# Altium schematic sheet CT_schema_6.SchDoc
size 299 x 185 mm
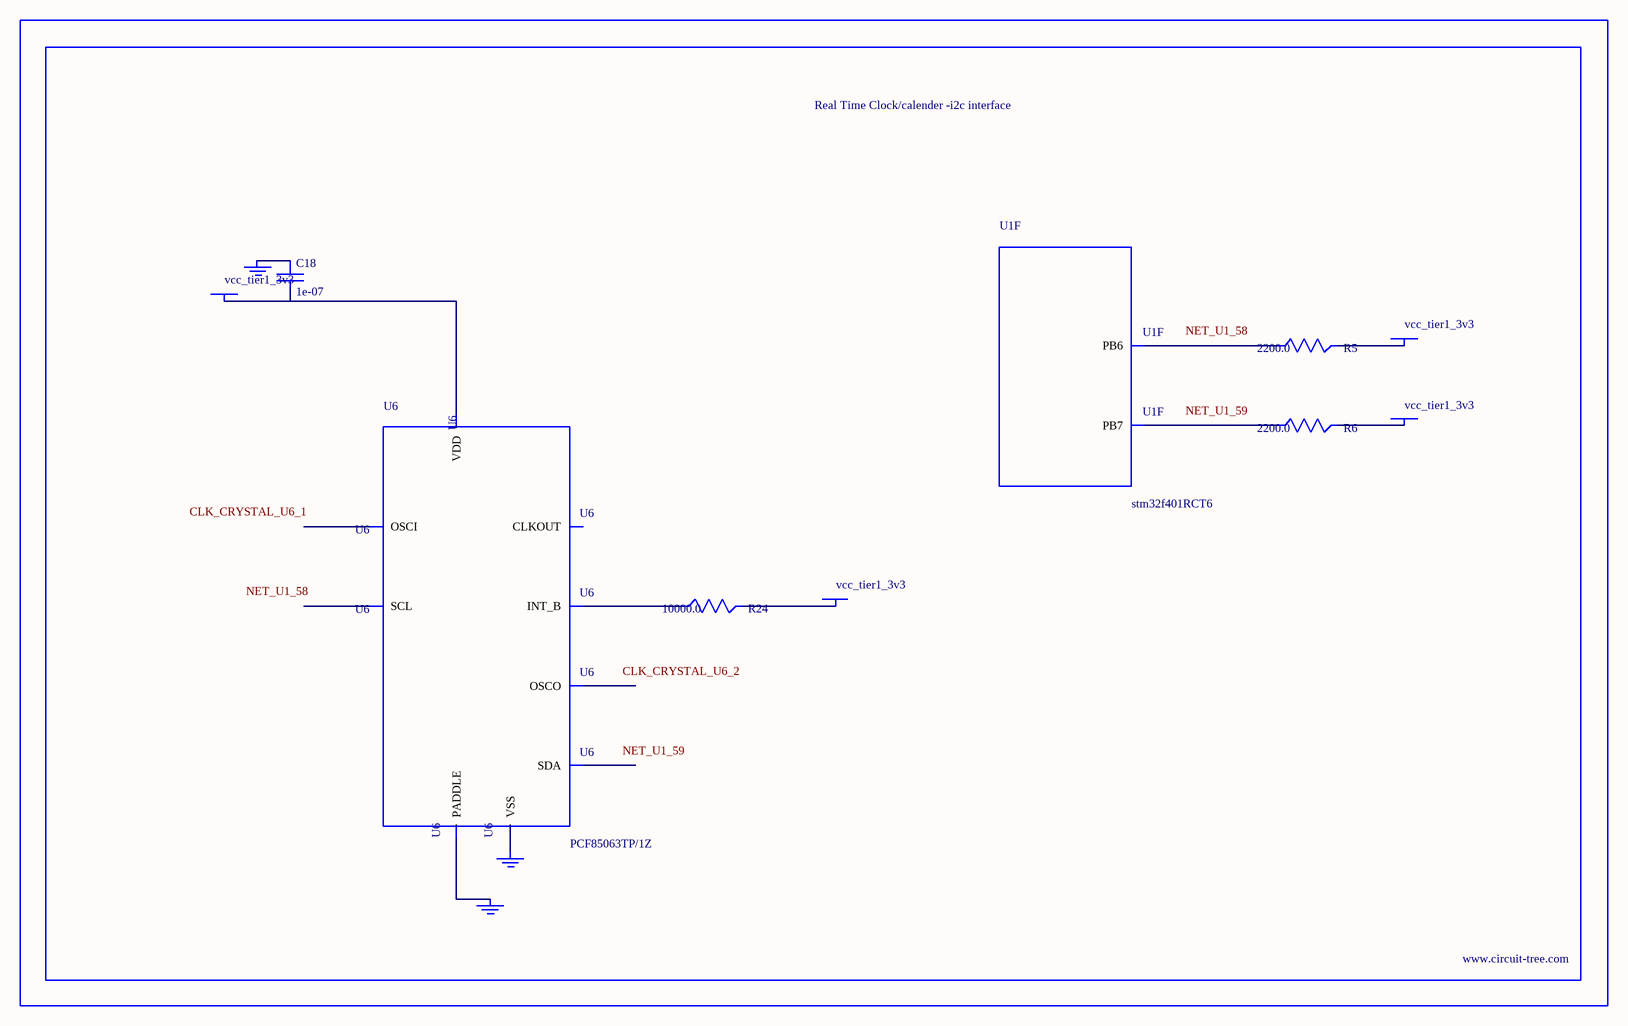
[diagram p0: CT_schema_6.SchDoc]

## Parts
BORDER5  (no value)
C18  1e-07  [C0402]
GND_INSTANCE_5_0  (no value)
GND_INSTANCE_5_1  (no value)
GND_INSTANCE_5_2  (no value)
POWER_INSTANCE_5_0  vcc_tier1_3v3
POWER_INSTANCE_5_1  vcc_tier1_3v3
POWER_INSTANCE_5_2  vcc_tier1_3v3
POWER_INSTANCE_5_3  vcc_tier1_3v3
R5  2200.0  [R0603]
R6  2200.0  [R0603]
R24  10000.0  [R0603]
U1  stm32f401RCT6  [LQFP64]  (part F of 9)
U6  PCF85063TP/1Z  [SON-8]

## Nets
NetC18_1: C18.1 GND_INSTANCE_5_0.0(GND)
NetC18_2: C18.2 POWER_INSTANCE_5_1.0(PWR) U6.8(VDD)
NetGND_INSTANCE_5_1_0: GND_INSTANCE_5_1.0(GND) U6.PAD(PADDLE)
NetGND_INSTANCE_5_2_0: GND_INSTANCE_5_2.0(GND) U6.4(VSS)
NetPOWER_INSTANCE_5_0_0: POWER_INSTANCE_5_0.0(PWR) R24.2
NetPOWER_INSTANCE_5_2_0: POWER_INSTANCE_5_2.0(PWR) R5.2
NetPOWER_INSTANCE_5_3_0: POWER_INSTANCE_5_3.0(PWR) R6.2
NetR5_1: R5.1 U1.58(PB6)
NetR6_1: R6.1 U1.59(PB7)
NetR24_1: R24.1 U6.3(INT_B)

Not connected (* = marked no-connect by the designer): U6 1(OSCI) 2(OSCO) 5(SDA) 6(SCL) 7(CLKOUT)

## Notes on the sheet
- Labels drawn without touching a wire or pin: CLK_CRYSTAL_U6_1, CLK_CRYSTAL_U6_2, NET_U1_58, NET_U1_59

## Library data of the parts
BORDER5 = BORDER_PAGE5
C18 = C0402C104K3RACTU
GND_INSTANCE_5_0-GND_INSTANCE_5_2 = GND
POWER_INSTANCE_5_0-POWER_INSTANCE_5_3 = PWR
R5 R6 = RC0603JR-072K2L
R24 = RC0603JR-0710KL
